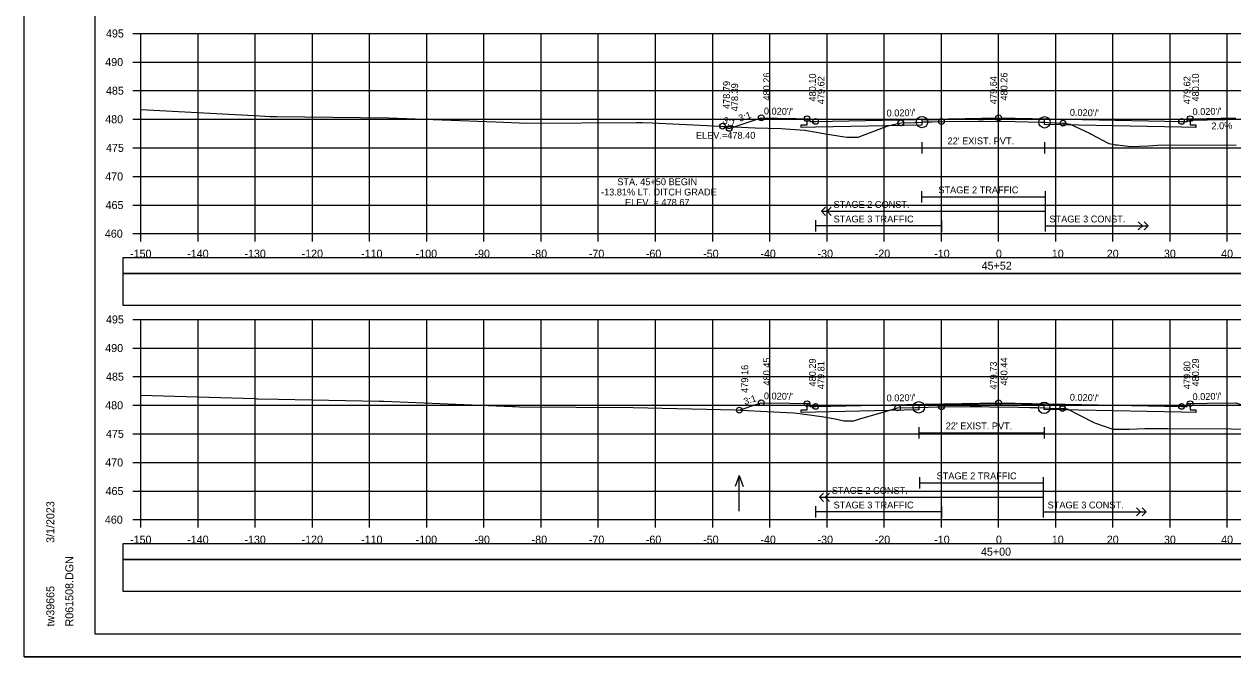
# Model space of a CAD drawing. Extents: x 1371057 to 1372761, y 380005 to 390517.
# Drawn here: x 1371390.5 to 1371601.8, y 382138.5 to 382249.1 of the extents above; entities that cross this region are included whole.
import ezdxf

# ---------------------------------------------------------------- set-up
doc = ezdxf.new("R2010")
doc.units = 0
for name, color, linetype in [('R_Alt Surface', 7, 'Continuous'), ('R_Axis', 7, 'Continuous'), ('R_Axis Annot', 7, 'Continuous'), ('R_Border', 7, 'Continuous'), ('R_Detour', 7, 'Continuous'), ('R_Dimension', 7, 'Continuous'), ('R_Drive', 7, 'Continuous'), ('R_Exist Surface', 7, 'Continuous'), ('R_Fin Surface', 7, 'Continuous'), ('R_Grid', 7, 'Continuous'), ('R_No Plot', 7, 'Continuous'), ('R_Striping', 7, 'Continuous'), ('R_Water', 7, 'Continuous'), ('R_Water Annot', 7, 'Continuous'), ('R_Xsect Elev', 7, 'Continuous'), ('R_Xsect Slope', 7, 'Continuous')]:
    doc.layers.add(name, color=color, linetype=linetype)

msp = doc.modelspace()

# ---------------------------------------------------------------- linework, layer by layer
at = {"layer": 'R_Alt Surface'}
for points in [[(1371594.37, 382232.54), (1371594.37, 382231.46), (1371595.37, 382231.44), (1371595.37, 382231.01), (1371592.87, 382231.06), (1371568.91, 382231.54), (1371568.91, 382232.37), (1371560.87, 382232.53), (1371547.47, 382232.26), (1371547.47, 382231.43), (1371528.87, 382231.06), (1371526.37, 382231.01), (1371526.37, 382231.44), (1371527.37, 382231.46), (1371527.37, 382232.54)], [(1371594.37, 382232.54), (1371594.37, 382231.46), (1371595.37, 382231.44), (1371595.37, 382231.01), (1371592.87, 382231.06), (1371568.91, 382231.54), (1371568.91, 382232.37), (1371560.87, 382232.53), (1371547.47, 382232.26), (1371547.47, 382231.43), (1371528.87, 382231.06), (1371526.37, 382231.01), (1371526.37, 382231.44), (1371527.37, 382231.46), (1371527.37, 382232.54)], [(1371547.47, 382228.45), (1371547.47, 382226.45)], [(1371547.47, 382227.45), (1371568.91, 382227.45)], [(1371568.91, 382228.45), (1371568.91, 382226.45)], [(1371594.37, 382182.72), (1371594.37, 382181.64), (1371595.37, 382181.62), (1371595.37, 382181.19), (1371592.87, 382181.24), (1371568.85, 382181.72), (1371568.85, 382182.55), (1371560.87, 382182.71), (1371546.91, 382182.44), (1371546.9, 382181.61), (1371528.87, 382181.24), (1371526.37, 382181.19), (1371526.37, 382181.62), (1371527.37, 382181.64), (1371527.37, 382182.72)], [(1371594.37, 382182.72), (1371594.37, 382181.64), (1371595.37, 382181.62), (1371595.37, 382181.19), (1371592.87, 382181.24), (1371568.85, 382181.72), (1371568.85, 382182.55), (1371560.87, 382182.71), (1371546.91, 382182.44), (1371546.9, 382181.61), (1371528.87, 382181.24), (1371526.37, 382181.19), (1371526.37, 382181.62), (1371527.37, 382181.64), (1371527.37, 382182.72)], [(1371546.91, 382178.63), (1371546.91, 382176.63)], [(1371568.85, 382178.63), (1371568.85, 382176.63)], [(1371546.91, 382177.63), (1371568.85, 382177.63)]]:
    msp.add_lwpolyline(points, dxfattribs=at)
at = {"layer": 'R_Axis'}
for p, q in [((1371409.47, 382247.44), (1371410.87, 382247.44)), ((1371410.87, 382212.44), (1371410.87, 382247.44)), ((1371409.47, 382242.44), (1371410.87, 382242.44)), ((1371409.47, 382237.44), (1371410.87, 382237.44)), ((1371409.47, 382232.44), (1371410.87, 382232.44)), ((1371409.47, 382227.44), (1371410.87, 382227.44)), ((1371409.47, 382222.44), (1371410.87, 382222.44)), ((1371409.47, 382217.44), (1371410.87, 382217.44)), ((1371409.47, 382212.44), (1371410.87, 382212.44)), ((1371410.87, 382212.44), (1371710.87, 382212.44)), ((1371410.87, 382211.04), (1371410.87, 382212.44)), ((1371420.87, 382211.04), (1371420.87, 382212.44)), ((1371430.87, 382211.04), (1371430.87, 382212.44)), ((1371440.87, 382211.04), (1371440.87, 382212.44)), ((1371450.87, 382211.04), (1371450.87, 382212.44)), ((1371460.87, 382211.04), (1371460.87, 382212.44)), ((1371470.87, 382211.04), (1371470.87, 382212.44)), ((1371480.87, 382211.04), (1371480.87, 382212.44)), ((1371490.87, 382211.04), (1371490.87, 382212.44)), ((1371500.87, 382211.04), (1371500.87, 382212.44)), ((1371510.87, 382211.04), (1371510.87, 382212.44)), ((1371520.87, 382211.04), (1371520.87, 382212.44)), ((1371530.87, 382211.04), (1371530.87, 382212.44)), ((1371540.87, 382211.04), (1371540.87, 382212.44)), ((1371550.87, 382211.04), (1371550.87, 382212.44)), ((1371560.87, 382211.04), (1371560.87, 382212.44)), ((1371570.87, 382211.04), (1371570.87, 382212.44)), ((1371580.87, 382211.04), (1371580.87, 382212.44)), ((1371590.87, 382211.04), (1371590.87, 382212.44)), ((1371600.87, 382211.04), (1371600.87, 382212.44)), ((1371409.47, 382197.44), (1371410.87, 382197.44)), ((1371410.87, 382162.44), (1371410.87, 382197.44)), ((1371409.47, 382192.44), (1371410.87, 382192.44)), ((1371409.47, 382187.44), (1371410.87, 382187.44)), ((1371409.47, 382182.44), (1371410.87, 382182.44)), ((1371409.47, 382177.44), (1371410.87, 382177.44)), ((1371409.47, 382172.44), (1371410.87, 382172.44)), ((1371409.47, 382167.44), (1371410.87, 382167.44)), ((1371409.47, 382162.44), (1371410.87, 382162.44)), ((1371410.87, 382162.44), (1371710.87, 382162.44)), ((1371410.87, 382161.04), (1371410.87, 382162.44)), ((1371420.87, 382161.04), (1371420.87, 382162.44)), ((1371430.87, 382161.04), (1371430.87, 382162.44)), ((1371440.87, 382161.04), (1371440.87, 382162.44)), ((1371450.87, 382161.04), (1371450.87, 382162.44)), ((1371460.87, 382161.04), (1371460.87, 382162.44)), ((1371470.87, 382161.04), (1371470.87, 382162.44)), ((1371480.87, 382161.04), (1371480.87, 382162.44)), ((1371490.87, 382161.04), (1371490.87, 382162.44)), ((1371500.87, 382161.04), (1371500.87, 382162.44)), ((1371510.87, 382161.04), (1371510.87, 382162.44)), ((1371520.87, 382161.04), (1371520.87, 382162.44)), ((1371530.87, 382161.04), (1371530.87, 382162.44)), ((1371540.87, 382161.04), (1371540.87, 382162.44)), ((1371550.87, 382161.04), (1371550.87, 382162.44)), ((1371560.87, 382161.04), (1371560.87, 382162.44)), ((1371570.87, 382161.04), (1371570.87, 382162.44)), ((1371580.87, 382161.04), (1371580.87, 382162.44)), ((1371590.87, 382161.04), (1371590.87, 382162.44)), ((1371600.87, 382161.04), (1371600.87, 382162.44))]:
    msp.add_line(p, q, dxfattribs=at)
at = {"layer": 'R_Border'}
for p, q in [((1371402.87, 382142.44), (1371402.87, 382347.9)), ((1371402.87, 382142.44), (1371402.87, 382142.44)), ((1371719.05, 382142.44), (1371402.87, 382142.44))]:
    msp.add_line(p, q, dxfattribs=at)
at = {"layer": 'R_Detour'}
for points in [[(1371407.72, 382205.49), (1371714.03, 382205.49), (1371714.03, 382208.19), (1371407.72, 382208.19)], [(1371407.72, 382155.49), (1371714.03, 382155.49), (1371714.03, 382158.19), (1371407.72, 382158.19)]]:
    msp.add_lwpolyline(points, close=True, dxfattribs=at)
at = {"layer": 'R_Dimension'}
for points in [[(1371407.72, 382199.96), (1371714.03, 382199.96), (1371714.03, 382205.49), (1371407.72, 382205.49)], [(1371407.72, 382149.96), (1371714.03, 382149.96), (1371714.03, 382155.49), (1371407.72, 382155.49)]]:
    msp.add_lwpolyline(points, close=True, dxfattribs=at)
at = {"layer": 'R_Drive'}
for p, q in [((1371593.87, 382232.04), (1371594.37, 382232.29)), ((1371594.37, 382232.29), (1371606.37, 382232.53))]:
    msp.add_line(p, q, dxfattribs=at)
at = {"layer": 'R_Exist Surface'}
for points in [[(1371410.87, 382234.17), (1371430.7, 382233.08), (1371433.48, 382232.94), (1371434.64, 382232.93), (1371454.18, 382232.7), (1371472.96, 382231.97), (1371478.35, 382231.75), (1371497.55, 382231.87), (1371498.53, 382231.87), (1371500.27, 382231.8), (1371518.3, 382230.96), (1371522.87, 382230.8), (1371526.97, 382230.54), (1371529.05, 382230.2), (1371530.59, 382229.92), (1371533.9, 382229.39), (1371534.36, 382229.32), (1371536.28, 382229.28), (1371536.31, 382229.28), (1371540.75, 382230.97), (1371541.71, 382231.32), (1371542.28, 382231.45), (1371543.77, 382231.81), (1371546.2, 382231.9), (1371547.47, 382231.95), (1371547.47, 382231.95), (1371547.72, 382231.96), (1371549.25, 382232), (1371551.29, 382232.03), (1371557.32, 382232.13), (1371558.1, 382232.12), (1371558.23, 382232.12), (1371558.23, 382232.12), (1371563.78, 382232.04), (1371566.03, 382232), (1371568.19, 382231.94), (1371568.38, 382231.93), (1371568.91, 382231.91), (1371569.57, 382231.87), (1371572.13, 382231.76), (1371572.43, 382231.75), (1371573.05, 382231.65), (1371573.41, 382231.56), (1371576.88, 382229.94), (1371576.89, 382229.93), (1371577.05, 382229.85), (1371579.94, 382228.34), (1371580.17, 382228.21), (1371580.86, 382228.07), (1371581.28, 382227.98), (1371581.64, 382227.95), (1371583.99, 382227.69), (1371587.03, 382227.81), (1371589.46, 382227.96), (1371602.41, 382227.92)], [(1371410.87, 382184.21), (1371430.74, 382183.59), (1371431.17, 382183.58), (1371431.39, 382183.57), (1371434.91, 382183.51), (1371452.54, 382183.18), (1371453.35, 382183.18), (1371475.89, 382182.23), (1371476.34, 382182.2), (1371477.07, 382182.19), (1371496.96, 382182.06), (1371514.79, 382181.62), (1371515.78, 382181.6), (1371525, 382181.1), (1371525.57, 382181.07), (1371526.11, 382181), (1371530.29, 382180.42), (1371532.57, 382180.01), (1371533.82, 382179.74), (1371535.26, 382179.7), (1371535.57, 382179.7), (1371536.61, 382180.04), (1371541.28, 382181.41), (1371541.88, 382181.56), (1371543.22, 382181.96), (1371546.22, 382182.05), (1371546.91, 382182.07), (1371550.21, 382182.14), (1371551.5, 382182.17), (1371555.89, 382182.21), (1371557.2, 382182.22), (1371557.81, 382182.21), (1371557.91, 382182.21), (1371557.91, 382182.21), (1371557.91, 382182.21), (1371559.33, 382182.19), (1371564.37, 382182.11), (1371566.35, 382182.07), (1371567.57, 382182.03), (1371568.85, 382181.98), (1371569.71, 382181.95), (1371572.04, 382181.86), (1371572.6, 382181.87), (1371572.84, 382181.82), (1371577.53, 382179.44), (1371577.82, 382179.3), (1371579.31, 382178.8), (1371580.83, 382178.28), (1371580.93, 382178.28), (1371583.27, 382178.25), (1371583.79, 382178.26), (1371586.47, 382178.39), (1371590.46, 382178.36), (1371601.57, 382178.32), (1371608.07, 382178.16)]]:
    msp.add_lwpolyline(points, dxfattribs=at)
at = {"layer": 'R_Fin Surface'}
for points in [[(1371512.59, 382231.23), (1371513.77, 382230.83), (1371516.89, 382231.88), (1371519.37, 382232.7), (1371522.14, 382232.65), (1371524.37, 382232.6), (1371525.47, 382232.58), (1371527.37, 382232.54), (1371527.87, 382232.54), (1371527.88, 382232.04), (1371528.32, 382232.05), (1371528.87, 382232.06), (1371560.87, 382232.7), (1371560.87, 382232.7), (1371575.56, 382232.41), (1371592.86, 382232.06), (1371592.87, 382232.06), (1371593.87, 382232.04), (1371593.87, 382232.3), (1371593.87, 382232.54), (1371594.37, 382232.54), (1371597.29, 382232.6), (1371597.37, 382232.6), (1371602.37, 382232.7)], [(1371515.53, 382181.6), (1371518.78, 382182.69), (1371519.37, 382182.88), (1371524.37, 382182.78), (1371527.37, 382182.72), (1371527.74, 382182.72), (1371527.87, 382182.72), (1371527.88, 382182.22), (1371528.87, 382182.24), (1371544.82, 382182.56), (1371560.87, 382182.88), (1371560.87, 382182.88), (1371592.87, 382182.24), (1371592.87, 382182.24), (1371593.47, 382182.23), (1371593.87, 382182.22), (1371593.87, 382182.54), (1371593.87, 382182.72), (1371593.99, 382182.72), (1371594.37, 382182.72), (1371597.37, 382182.78), (1371602.37, 382182.88), (1371602.37, 382182.88), (1371617.52, 382177.83)]]:
    msp.add_lwpolyline(points, dxfattribs=at)
at = {"layer": 'R_Grid'}
for p, q in [((1371410.87, 382247.44), (1371710.87, 382247.44)), ((1371410.87, 382212.44), (1371410.87, 382247.44)), ((1371420.87, 382212.44), (1371420.87, 382247.44)), ((1371430.87, 382212.44), (1371430.87, 382247.44)), ((1371440.87, 382212.44), (1371440.87, 382247.44)), ((1371450.87, 382212.44), (1371450.87, 382247.44)), ((1371460.87, 382212.44), (1371460.87, 382247.44)), ((1371470.87, 382212.44), (1371470.87, 382247.44)), ((1371480.87, 382212.44), (1371480.87, 382247.44)), ((1371490.87, 382212.44), (1371490.87, 382247.44)), ((1371500.87, 382212.44), (1371500.87, 382247.44)), ((1371510.87, 382212.44), (1371510.87, 382247.44)), ((1371520.87, 382212.44), (1371520.87, 382247.44)), ((1371530.87, 382212.44), (1371530.87, 382247.44)), ((1371540.87, 382212.44), (1371540.87, 382247.44)), ((1371550.87, 382212.44), (1371550.87, 382247.44)), ((1371560.87, 382212.44), (1371560.87, 382247.44)), ((1371570.87, 382212.44), (1371570.87, 382247.44)), ((1371580.87, 382212.44), (1371580.87, 382247.44)), ((1371590.87, 382212.44), (1371590.87, 382247.44)), ((1371600.87, 382212.44), (1371600.87, 382247.44)), ((1371410.87, 382242.44), (1371710.87, 382242.44)), ((1371410.87, 382237.44), (1371710.87, 382237.44)), ((1371410.87, 382232.44), (1371710.87, 382232.44)), ((1371410.87, 382227.44), (1371710.87, 382227.44)), ((1371410.87, 382222.44), (1371710.87, 382222.44)), ((1371410.87, 382217.44), (1371710.87, 382217.44)), ((1371410.87, 382212.44), (1371710.87, 382212.44)), ((1371410.87, 382197.44), (1371710.87, 382197.44)), ((1371410.87, 382162.44), (1371410.87, 382197.44)), ((1371420.87, 382162.44), (1371420.87, 382197.44)), ((1371430.87, 382162.44), (1371430.87, 382197.44)), ((1371440.87, 382162.44), (1371440.87, 382197.44)), ((1371450.87, 382162.44), (1371450.87, 382197.44)), ((1371460.87, 382162.44), (1371460.87, 382197.44)), ((1371470.87, 382162.44), (1371470.87, 382197.44)), ((1371480.87, 382162.44), (1371480.87, 382197.44)), ((1371490.87, 382162.44), (1371490.87, 382197.44)), ((1371500.87, 382162.44), (1371500.87, 382197.44)), ((1371510.87, 382162.44), (1371510.87, 382197.44)), ((1371520.87, 382162.44), (1371520.87, 382197.44)), ((1371530.87, 382162.44), (1371530.87, 382197.44)), ((1371540.87, 382162.44), (1371540.87, 382197.44)), ((1371550.87, 382162.44), (1371550.87, 382197.44)), ((1371560.87, 382162.44), (1371560.87, 382197.44)), ((1371570.87, 382162.44), (1371570.87, 382197.44)), ((1371580.87, 382162.44), (1371580.87, 382197.44)), ((1371590.87, 382162.44), (1371590.87, 382197.44)), ((1371600.87, 382162.44), (1371600.87, 382197.44)), ((1371410.87, 382192.44), (1371710.87, 382192.44)), ((1371410.87, 382187.44), (1371710.87, 382187.44)), ((1371410.87, 382182.44), (1371710.87, 382182.44)), ((1371410.87, 382177.44), (1371710.87, 382177.44)), ((1371410.87, 382172.44), (1371710.87, 382172.44)), ((1371410.87, 382167.44), (1371710.87, 382167.44)), ((1371410.87, 382162.44), (1371710.87, 382162.44))]:
    msp.add_line(p, q, dxfattribs=at)
at = {"layer": 'R_No Plot'}
msp.add_line((1371390.47, 382138.46), (1371723.8, 382138.46), dxfattribs=at)
for points in [[(1371390.46, 382351.79), (1371723.8, 382351.79), (1371723.8, 382138.46), (1371390.46, 382138.46)], [(1371636.79, 382347.9), (1371656.41, 382347.9), (1371656.41, 382338.02), (1371672.52, 382338.02), (1371695.72, 382338.02), (1371695.84, 382309.86), (1371719.05, 382309.86), (1371719.05, 382142.44), (1371402.87, 382142.44), (1371402.87, 382347.9)]]:
    msp.add_lwpolyline(points, close=True, dxfattribs=at)
for centre, radius in [((1371512.59, 382231.23), 0.5), ((1371519.37, 382232.7), 0.5), ((1371527.37, 382232.54), 0.5), ((1371528.87, 382232.06), 0.5), ((1371543.77, 382231.81), 0.5), ((1371547.47, 382231.95), 1), ((1371550.87, 382232.03), 0.5), ((1371560.87, 382232.7), 0.5), ((1371568.91, 382231.91), 1), ((1371572.13, 382231.76), 0.5), ((1371592.87, 382232.06), 0.5), ((1371594.37, 382232.54), 0.5), ((1371513.77, 382230.83), 0.5), ((1371519.37, 382182.88), 0.5), ((1371527.37, 382182.72), 0.5), ((1371546.91, 382182.07), 1), ((1371560.87, 382182.88), 0.5), ((1371568.85, 382181.98), 1), ((1371594.37, 382182.72), 0.5), ((1371515.53, 382181.6), 0.5), ((1371528.87, 382182.24), 0.5), ((1371543.22, 382181.96), 0.5), ((1371550.88, 382182.16), 0.5), ((1371572.04, 382181.86), 0.5), ((1371592.87, 382182.24), 0.5)]:
    msp.add_circle(centre, radius, dxfattribs=at)
at = {"layer": 'R_Striping'}
for p, q in [((1371547.37, 382219.89), (1371547.37, 382217.89)), ((1371547.37, 382218.89), (1371569.01, 382218.89)), ((1371569.01, 382219.89), (1371569.01, 382212.8)), ((1371529.88, 382216.35), (1371530.59, 382217.05)), ((1371530.88, 382216.35), (1371531.59, 382217.05)), ((1371528.87, 382214.8), (1371528.87, 382212.8)), ((1371529.88, 382216.35), (1371569.01, 382216.35)), ((1371530.59, 382215.64), (1371529.88, 382216.35)), ((1371531.59, 382215.64), (1371530.88, 382216.35)), ((1371550.87, 382214.8), (1371550.87, 382212.8)), ((1371586.01, 382213.8), (1371585.3, 382214.51)), ((1371587.01, 382213.8), (1371586.3, 382214.51)), ((1371550.87, 382213.8), (1371528.87, 382213.8)), ((1371569.01, 382213.8), (1371587.01, 382213.8)), ((1371569.04, 382213.8), (1371579.04, 382213.8)), ((1371585.3, 382213.1), (1371586.01, 382213.8)), ((1371586.3, 382213.1), (1371587.01, 382213.8)), ((1371547.06, 382169.89), (1371547.06, 382167.89)), ((1371547.06, 382168.89), (1371568.69, 382168.89)), ((1371568.69, 382169.89), (1371568.69, 382162.8)), ((1371529.57, 382166.35), (1371530.28, 382167.05)), ((1371529.57, 382166.35), (1371568.69, 382166.35)), ((1371530.28, 382165.64), (1371529.57, 382166.35)), ((1371530.57, 382166.35), (1371531.28, 382167.05)), ((1371531.28, 382165.64), (1371530.57, 382166.35)), ((1371528.87, 382164.8), (1371528.87, 382162.8)), ((1371550.87, 382163.8), (1371528.87, 382163.8)), ((1371550.87, 382164.8), (1371550.87, 382162.8)), ((1371568.69, 382163.8), (1371586.69, 382163.8)), ((1371568.73, 382163.8), (1371578.73, 382163.8)), ((1371585.69, 382163.8), (1371584.99, 382164.51)), ((1371584.99, 382163.1), (1371585.69, 382163.8)), ((1371586.69, 382163.8), (1371585.99, 382164.51)), ((1371585.99, 382163.1), (1371586.69, 382163.8))]:
    msp.add_line(p, q, dxfattribs=at)
at = {"layer": 'R_Water Annot'}
for p, q in [((1371515.53, 382170.18), (1371514.83, 382168.26)), ((1371515.53, 382163.9), (1371515.53, 382170.18)), ((1371515.53, 382170.18), (1371516.23, 382168.26))]:
    msp.add_line(p, q, dxfattribs=at)
at = {"layer": 'R_Xsect Elev'}
for p, q in [((1371560.87, 382232.08), (1371560.87, 382242.08)), ((1371560.87, 382182.17), (1371560.87, 382192.17))]:
    msp.add_line(p, q, dxfattribs=at)

# ---------------------------------------------------------------- texts
at = {"layer": 'R_Axis Annot'}
for s, p in [('495', (1371404.77, 382246.74)), ('490', (1371404.64, 382241.74)), ('485', (1371404.77, 382236.74)), ('480', (1371404.64, 382231.74)), ('475', (1371404.77, 382226.74)), ('470', (1371404.64, 382221.74)), ('465', (1371404.7, 382216.74)), ('460', (1371404.58, 382211.74)), ('-150', (1371408.98, 382208.24)), ('-140', (1371418.98, 382208.24)), ('-130', (1371428.98, 382208.24)), ('-120', (1371438.98, 382208.24)), ('-110', (1371449.38, 382208.24)), ('-100', (1371458.93, 382208.24)), ('-90', (1371469.21, 382208.24)), ('-80', (1371479.21, 382208.24)), ('-70', (1371489.21, 382208.24)), ('-60', (1371499.18, 382208.24)), ('-50', (1371509.21, 382208.24)), ('-40', (1371519.21, 382208.24)), ('-30', (1371529.21, 382208.24)), ('-20', (1371539.21, 382208.24)), ('-10', (1371549.61, 382208.24)), ('0', (1371560.41, 382208.24)), ('10', (1371570.18, 382208.24)), ('20', (1371579.79, 382208.24)), ('30', (1371589.79, 382208.24)), ('40', (1371599.79, 382208.24)), ('45+52', (1371557.91, 382206.14)), ('495', (1371404.77, 382196.74)), ('490', (1371404.64, 382191.74)), ('485', (1371404.77, 382186.74)), ('480', (1371404.64, 382181.74)), ('475', (1371404.77, 382176.74)), ('470', (1371404.64, 382171.74)), ('465', (1371404.7, 382166.74)), ('460', (1371404.58, 382161.74)), ('-150', (1371408.98, 382158.24)), ('-140', (1371418.98, 382158.24)), ('-130', (1371428.98, 382158.24)), ('-120', (1371438.98, 382158.24)), ('-110', (1371449.38, 382158.24)), ('-100', (1371458.93, 382158.24)), ('-90', (1371469.21, 382158.24)), ('-80', (1371479.21, 382158.24)), ('-70', (1371489.21, 382158.24)), ('-60', (1371499.18, 382158.24)), ('-50', (1371509.21, 382158.24)), ('-40', (1371519.21, 382158.24)), ('-30', (1371529.21, 382158.24)), ('-20', (1371539.21, 382158.24)), ('-10', (1371549.61, 382158.24)), ('0', (1371560.41, 382158.24)), ('10', (1371570.18, 382158.24)), ('20', (1371579.79, 382158.24)), ('30', (1371589.79, 382158.24)), ('40', (1371599.79, 382158.24)), ('45+00', (1371557.79, 382156.14))]:
    msp.add_text(s, height=1.4, dxfattribs=at).set_placement(p)
at = {"layer": 'R_Border'}
for s, p in [('3/1/2023', (1371395.74, 382158.37)), ('R061508.DGN', (1371399.06, 382143.76)), ('tw39665', (1371395.74, 382143.76))]:
    msp.add_text(s, height=1.4, rotation=90, dxfattribs=at).set_placement(p)
at = {"layer": 'R_Striping'}
for s, p in [('STAGE 2 TRAFFIC', (1371550.34, 382219.49)), ('STAGE 2 CONST.', (1371532.01, 382216.95)), ('STAGE 3 TRAFFIC', (1371532.02, 382214.4)), ('STAGE 3 CONST.', (1371569.76, 382214.4)), ('STAGE 2 TRAFFIC', (1371550.03, 382169.49)), ('STAGE 2 CONST.', (1371531.7, 382166.95)), ('STAGE 3 TRAFFIC', (1371532.02, 382164.4)), ('STAGE 3 CONST.', (1371569.45, 382164.4))]:
    msp.add_text(s, height=1.2, dxfattribs=at).set_placement(p)
at = {"layer": 'R_Water'}
for p in [(1371551.95, 382228.05), (1371551.63, 382178.23)]:
    msp.add_text("22' EXIST. PVT.", height=1.2, dxfattribs=at).set_placement(p)
at = {"layer": 'R_Xsect Elev'}
for s, rotation, p in [('480.26', 90, (1371520.92, 382235.7)), ('480.10', 90, (1371528.92, 382235.54)), ('479.62', 90, (1371530.42, 382235.06)), ('479.64', 90, (1371560.57, 382235.08)), ('480.26', 90, (1371562.42, 382235.7)), ('479.62', 90, (1371594.42, 382235.06)), ('480.10', 90, (1371595.92, 382235.54)), ('478.79', 90, (1371513.9, 382234.23)), ('478.39', 90, (1371515.32, 382233.83)), ('2.0%', 1.1458, (1371598.1, 382230.66)), ('479.16', 90, (1371517.08, 382184.6)), ('480.45', 90, (1371520.92, 382185.88)), ('480.29', 90, (1371528.92, 382185.72)), ('479.81', 90, (1371530.42, 382185.24)), ('479.73', 90, (1371560.57, 382185.17)), ('480.44', 90, (1371562.42, 382185.88)), ('479.80', 90, (1371594.42, 382185.24)), ('480.29', 90, (1371595.92, 382185.72))]:
    msp.add_text(s, height=1.2, rotation=rotation, dxfattribs=at).set_placement(p)
for s, p in [('ELEV.=478.40', (1371507.94, 382229.03)), ('STA. 45+50 BEGIN ', (1371494.19, 382220.91)), ('-13.81% LT. DITCH GRADE', (1371491.34, 382219.11)), ('ELEV. = 478.67', (1371495.54, 382217.31))]:
    msp.add_text(s, height=1.2, dxfattribs=at).set_placement(p)
at = {"layer": 'R_Xsect Slope'}
for s, rotation, p in [('3:1', 18.434, (1371515.62, 382231.98)), ("0.020'/'", 358.8543, (1371519.82, 382233.29)), ("0.020'/'", 1.1458, (1371541.3, 382232.91)), ("0.020'/'", 358.8542, (1371573.32, 382233.05)), ("0.020'/'", 1.1457, (1371594.8, 382233.15)), ('3:1', 341.5852, (1371512.55, 382231.77)), ('3:1', 18.4321, (1371516.51, 382182.46)), ("0.020'/'", 358.8543, (1371519.82, 382183.48)), ("0.020'/'", 1.1458, (1371541.3, 382183.09)), ("0.020'/'", 358.8542, (1371573.32, 382183.24)), ("0.020'/'", 1.1457, (1371594.8, 382183.33))]:
    msp.add_text(s, height=1.2, rotation=rotation, dxfattribs=at).set_placement(p)

doc.saveas('drawing.dxf')
